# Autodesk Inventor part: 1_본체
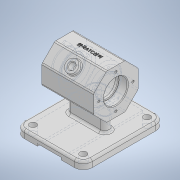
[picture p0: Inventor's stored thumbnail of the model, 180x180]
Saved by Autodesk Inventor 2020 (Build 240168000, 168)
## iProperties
Created: 2022-10
Part Number: 1_본체
Material: 일반
Document SubType Name: Modeling
Designer: USER
Density: 1 g/cm^3
Appearance: 기본값
Author: USER
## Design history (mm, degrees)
sketch "스케치1"
  geometry: L1 (46, 55)-(-46, 55); L2 (-46, 55)-(-46, -55); L3 (-46, -55)-(46, -55); L4 (46, -55)-(46, 55); L5 (46, 55)-(-46, -55); L6 (-46, 55)-(46, -55); 1 further point
  constraints: 12 end point, 2 midpoint, 2 parallel, 1 horizontal, 1 perpendicular
  dimensions: "d0" = 92 distance of L2.end L3.end; "d1" = 110 distance of L3.end L1.start
extrude "돌출1" new body sketch "스케치1" distance "d2" = 10; taper "d3" = 0 deg
sketch "스케치2"
  geometry: L1 (30, 3)-(62, 3); L2 (62, 3)-(62, 0); L3 (62, 0)-(30, 0); L4 (30, 0)-(30, 3); L5 (0, 0)-(92, 0) reference; 2 further points
  constraints: 8 end point, 2 midpoint, 2 parallel, 1 horizontal, 1 perpendicular
  dimensions: "d4" = 32 distance of L2.end L3.end; "d5" = 3 distance of L1.end L2.end
extrude "돌출2" cut sketch "스케치2" extent not by distance; stored distance "d6" = 0; taper "d7" = 0 deg
fillet "모깎기1" dims "d8" = 12
sketch "스케치3"
  geometry: L1 (74.426, 30)-(92, 12.426); L2 (92, 12.426)-(92, -12.426); L3 (92, -12.426)-(74.426, -30); L4 (74.426, -30)-(49.574, -30); L5 (49.574, -30)-(32, -12.426); L6 (32, -12.426)-(32, 12.426); L7 (32, 12.426)-(49.574, 30); L8 (49.574, 30)-(74.426, 30); L9 (0, -55)-(0, -43) reference; L10 (0, 0)-(62, 0); C1 r 30 at (62, 0); 1 further point
  constraints: 18 end point, 2 coincident, 2 horizontal, 1 centre point, 1 tangent, 17 other
  dimensions: "d9" = 62 distance from line of L9 point (62, 0); "d10" = 60 diameter of C1
extrude "돌출3" join sketch "스케치3" stored distance "d11" = 70; taper "d12" = 0 deg
sketch "스케치4"
  geometry: L1 (-20, 0)-(20, 0); L2 (-20, -6)-(20, -6); L3 (20, 6)-(-20, 6); A1 r 6 centre (-20, 0) between (-20, 6) and (-20, -6); A2 r 6 centre (20, 0) between (20, -6) and (20, 6); 2 further points
  constraints: 8 end point, 4 point on circle, 4 tangent, 2 centre point, 1 coincident, 1 horizontal, 1 midpoint, 1 parallel
  dimensions: "d13" = 40 distance of L1.start L1.end; "d14" = 12 distance between parallel lines of L3 L2
extrude "돌출4" join sketch "스케치4" stored distance "d15" = 70; taper "d16" = 0 deg
sketch "스케치5"
  geometry: L1 (74.426, 30)-(92, 12.426) reference; L2 (83.213, 21.213)-(88.87, 15.556); L3 (88.87, 15.556)-(92.406, 19.092); L4 (92.406, 19.092)-(86.749, 24.749); L5 (86.749, 24.749)-(83.213, 21.213); 1 further point
  constraints: 8 end point, 2 parallel, 1 midpoint, 1 perpendicular, 1 point on line
  dimensions: "d17" = 16 diameter of L3 L5; "d18" = 5 distance between parallel lines of L1 L4
revolve "회전1" sketch "스케치5" stored, may be unused: angle "d19" = 90 deg
sketch "스케치6"
  geometry: L1 (-35, 74.426)-(-35, 49.574) reference; L2 (-35, 92)-(35, 92) reference; L3 (-35, 62)-(0, 62); L4 (0, 92)-(0, 62); L5 (-20, 62)-(20, 62); L6 (20, 62)-(20, 84); L7 (17, 87)-(-17, 87); L8 (-20, 84)-(-20, 62); A1 r 3 centre (-17, 84) between (-17, 87) and (-20, 84); A2 r 3 centre (17, 84) between (20, 84) and (17, 87); 3 further points
  constraints: 12 end point, 4 point on circle, 4 point on line, 4 tangent, 3 midpoint, 2 centre point, 2 horizontal, 2 parallel, 1 equal radius, 1 perpendicular, 1 vertical
  dimensions: "d20" = 50 diameter of L7 L5; "d21" = 40 distance of point (20, 87) point (-20, 87); "d22" = 3 radius of A1
revolve "회전2" sketch "스케치6" stored, may be unused: angle "d23" = 90 deg
sketch "스케치7"
  geometry: L1 (-35, 74.426)-(-35, 49.574) reference; L2 (-35, 62)-(-20, 62); L3 (-20, 84)-(-20, 40) reference; L4 (-35, 62)-(-35, 78); L5 (-35, 78)-(-23, 78); L6 (-23, 78)-(-23, 76); L7 (-23, 76)-(-20, 76); L8 (-20, 76)-(-20, 62); 1 further point
  constraints: 12 end point, 3 perpendicular, 2 midpoint, 2 vertical, 1 point on line
  dimensions: "d24" = 32 diameter of L5 L2; "d25" = 28 diameter of L7 L2; "d26" = 12 distance between parallel lines of L4 L6
revolve "회전3" sketch "스케치7" stored, may be unused: angle "d27" = 90 deg
chamfer "모따기1" distance "d28" = 1; stored, may be unused: second distance "d29" = 2, angle "d30" = 45 deg
fillet "모깎기2" dims "d31" = 0.3
sketch "스케치8" dims "d32" = 46
  geometry: L1 (0, 62)-(0, 85); C1 r 17 at (0, 62) reference; 2 further points
  constraints: 2 coincident, 2 end point, 1 vertical, 1 vertical alignment, 2 other
hole "구멍1" sketch "스케치8" at (0, 85) diameter "d33" = 3.242; stored, may be unused: countersink angle "d37" = 90 deg, drill point angle "d39" = 118 deg; dims "d34" = 8, "d35" = 4, "d36" = 2, "d38" = 10
sketch "스케치9"
  geometry: C1 r 8 at (0, 0) reference; C2 r 4 at (0, 0); 1 further point
  constraints: 1 centre point, 1 coincident
  dimensions: "d43" = 8 diameter of C2
extrude "돌출5" cut sketch "스케치9" stored distance "d44" = 70; taper "d45" = 0 deg
sketch "스케치10"
  geometry: L1 (20, -6)-(-20, -6) reference; L2 (-20, 6)-(20, 6) reference; L3 (34, 55)-(-34, 55) reference; L4 (-46, 43)-(-46, -43) reference; L5 (-34, -55)-(34, -55) reference; L6 (46, -43)-(46, 43) reference; A1 r 6 centre (-20, 0) between (-20, 6) and (-20, -6) reference; A2 r 6 centre (20, 0) between (20, -6) and (20, 6) reference; A3 r 12 centre (-34, 43) between (-34, 55) and (-46, 43) reference; A4 r 12 centre (-34, -43) between (-46, -43) and (-34, -55) reference; A5 r 12 centre (34, -43) between (34, -55) and (46, -43) reference; A6 r 12 centre (34, 43) between (46, 43) and (34, 55) reference; 5 further points
  constraints: 4 coincident
hole "구멍2" sketch "스케치10" at (-34, 43), (34, 43), (34, -43), (-34, -43) diameter "d46" = 9; stored, may be unused: countersink angle "d50" = 90 deg, drill point angle "d52" = 118 deg; dims "d47" = 8, "d48" = 4, "d49" = 2, "d51" = 10
sketch "스케치11"
  geometry: L1 (18.408, 14.828)-(51.592, 14.828); L2 (51.592, 14.828)-(51.592, 10.025); L3 (51.592, 10.025)-(18.408, 10.025); L4 (18.408, 10.025)-(18.408, 14.828); 2 further points
  constraints: 1 coincident, 1 horizontal, 2 other
  dimensions: "d53" = 33.18318 distance of L1.start L1.end; "d54" = 4.80326 distance of L1.end L2.end; "d55" = 16.59159 distance from line of L2 point (35, 12.426) (= 0.5 x d53); "d56" = 2.40163 distance from line of point (35, 12.426) L3 (= 0.5 x d54)
feature "엠보싱1" sketch "스케치11" dims "d0" = 92, "d1" = 110, "d57" = 0.5, "d58" = 0
fillet "모깎기3" dims "d59" = 3
fillet "모깎기4" dims "d60" = 1
node "솔리드1"
mirror "미러1"
pattern_circular "원형 패턴1" dims angle "d41" = 360 deg
mirror "미러2"
node "투영된 루프1"
feature "A9D066F2-1C7D-4E18-AEED-F7BC21143FA4" dims "d46" = 9, "d47" = 8, "d48" = 4, "d49" = 2, "d50" = 90 deg, "d51" = 10, "d52" = 118 deg
